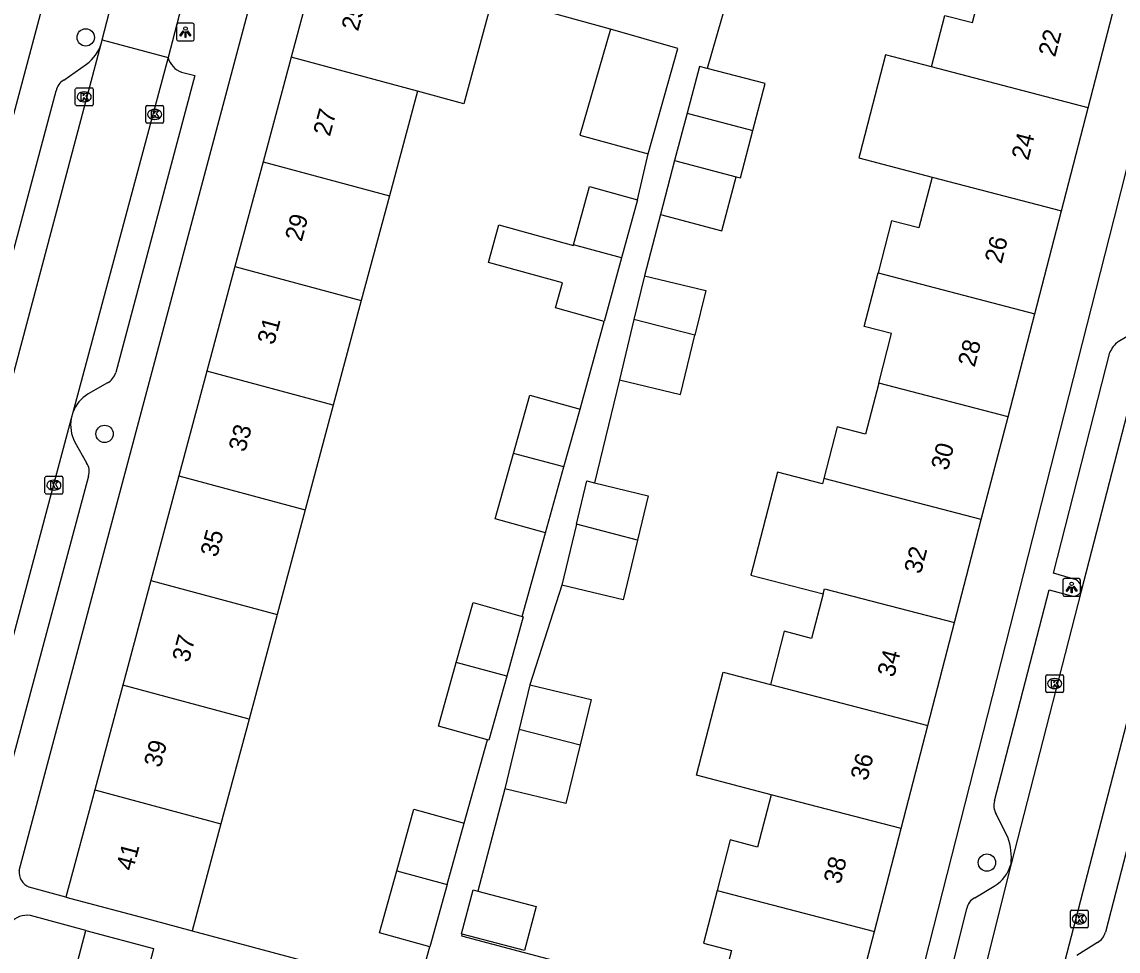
# Model space of a CAD drawing. Extents: x 163686 to 164493, y 382719 to 383870.
# Drawn here: x 163816.8 to 163878.6, y 383177.8 to 383230.2 of the extents above; entities that cross this region are included whole.
import ezdxf

# ---------------------------------------------------------------- set-up
doc = ezdxf.new("R2010")
doc.units = 0
for name, color, linetype in [('IMGEO_Boom', 7, 'Continuous'), ('IMGEO_Kolk', 7, 'Continuous'), ('IMGEO_Lichtpunt', 7, 'Continuous'), ('IMGEO_Pand', 7, 'Continuous'), ('IMGEO_Pand_nummerreeks', 7, 'Continuous'), ('IMGEO_Rijbaan_lokaal_open', 7, 'Continuous'), ('IMGEO_Voetpad_open', 7, 'Continuous')]:
    doc.layers.add(name, color=color, linetype=linetype)

msp = doc.modelspace()

# ---------------------------------------------------------------- linework, layer by layer
at = {"layer": 'IMGEO_Boom'}
for centre in [(163820.356, 383229.363), (163821.42, 383207), (163871.215, 383182.811)]:
    msp.add_circle(centre, 0.489, dxfattribs=at)
at = {"layer": 'IMGEO_Kolk'}
for p, q in [((163819.844, 383226.514), (163820.696, 383226.514)), ((163819.769, 383225.588), (163819.769, 383226.44)), ((163820.257, 383226.294), (163820.282, 383226.294)), ((163820.77, 383226.44), (163820.77, 383225.588)), ((163820.696, 383225.514), (163819.844, 383225.514)), ((163820.28, 383225.734), (163820.255, 383225.734)), ((163823.748, 383224.594), (163823.748, 383225.446)), ((163823.823, 383225.52), (163824.675, 383225.52)), ((163824.236, 383225.3), (163824.261, 383225.3)), ((163824.749, 383225.446), (163824.749, 383224.594)), ((163824.259, 383224.74), (163824.234, 383224.74)), ((163824.675, 383224.52), (163823.823, 383224.52)), ((163818.057, 383203.679), (163818.057, 383204.531)), ((163818.132, 383204.605), (163818.984, 383204.605)), ((163818.545, 383204.385), (163818.57, 383204.385)), ((163819.058, 383204.531), (163819.058, 383203.679)), ((163818.568, 383203.825), (163818.543, 383203.825)), ((163818.984, 383203.605), (163818.132, 383203.605)), ((163874.539, 383192.486), (163874.539, 383193.338)), ((163874.614, 383193.412), (163875.466, 383193.412)), ((163875.027, 383193.192), (163875.052, 383193.192)), ((163875.54, 383193.338), (163875.54, 383192.486)), ((163875.05, 383192.632), (163875.025, 383192.632)), ((163875.466, 383192.412), (163874.614, 383192.412)), ((163876.01, 383180.135), (163876.862, 383180.135)), ((163875.935, 383179.209), (163875.935, 383180.061)), ((163876.423, 383179.915), (163876.448, 383179.915)), ((163876.936, 383180.061), (163876.936, 383179.209)), ((163876.862, 383179.135), (163876.01, 383179.135)), ((163876.446, 383179.355), (163876.421, 383179.355))]:
    msp.add_line(p, q, dxfattribs=at)
for points in [[(163819.844, 383226.514), (163820.696, 383226.514)], [(163819.769, 383225.588), (163819.769, 383226.44)], [(163820.09, 383226.214), (163820.213, 383226.214), (163820.213, 383226.063), (163820.343, 383226.214), (163820.507, 383226.214), (163820.361, 383226.063), (163820.514, 383225.814), (163820.362, 383225.814), (163820.277, 383225.978), (163820.213, 383225.911), (163820.213, 383225.814), (163820.09, 383225.814), (163820.09, 383226.214)], [(163820.77, 383226.44), (163820.77, 383225.588)], [(163820.696, 383225.514), (163819.844, 383225.514)], [(163823.748, 383224.594), (163823.748, 383225.446)], [(163823.823, 383225.52), (163824.675, 383225.52)], [(163824.749, 383225.446), (163824.749, 383224.594)], [(163824.069, 383225.22), (163824.192, 383225.22), (163824.192, 383225.069), (163824.322, 383225.22), (163824.486, 383225.22), (163824.34, 383225.069), (163824.493, 383224.82), (163824.341, 383224.82), (163824.256, 383224.984), (163824.192, 383224.917), (163824.192, 383224.82), (163824.069, 383224.82), (163824.069, 383225.22)], [(163824.675, 383224.52), (163823.823, 383224.52)], [(163818.057, 383203.679), (163818.057, 383204.531)], [(163818.132, 383204.605), (163818.984, 383204.605)], [(163818.378, 383204.305), (163818.501, 383204.305), (163818.501, 383204.154), (163818.631, 383204.305), (163818.795, 383204.305), (163818.649, 383204.154), (163818.802, 383203.905), (163818.65, 383203.905), (163818.565, 383204.069), (163818.501, 383204.002), (163818.501, 383203.905), (163818.378, 383203.905), (163818.378, 383204.305)], [(163819.058, 383204.531), (163819.058, 383203.679)], [(163818.984, 383203.605), (163818.132, 383203.605)], [(163874.539, 383192.486), (163874.539, 383193.338)], [(163874.614, 383193.412), (163875.466, 383193.412)], [(163874.86, 383193.112), (163874.983, 383193.112), (163874.983, 383192.961), (163875.113, 383193.112), (163875.277, 383193.112), (163875.131, 383192.961), (163875.284, 383192.712), (163875.132, 383192.712), (163875.047, 383192.876), (163874.983, 383192.809), (163874.983, 383192.712), (163874.86, 383192.712), (163874.86, 383193.112)], [(163875.54, 383193.338), (163875.54, 383192.486)], [(163875.466, 383192.412), (163874.614, 383192.412)], [(163876.01, 383180.135), (163876.862, 383180.135)], [(163875.935, 383179.209), (163875.935, 383180.061)], [(163876.256, 383179.835), (163876.379, 383179.835), (163876.379, 383179.684), (163876.509, 383179.835), (163876.673, 383179.835), (163876.527, 383179.684), (163876.68, 383179.435), (163876.528, 383179.435), (163876.443, 383179.599), (163876.379, 383179.532), (163876.379, 383179.435), (163876.256, 383179.435), (163876.256, 383179.835)], [(163876.936, 383180.061), (163876.936, 383179.209)], [(163876.862, 383179.135), (163876.01, 383179.135)]]:
    msp.add_lwpolyline(points, dxfattribs=at)
for centre, start, end in [((163819.846, 383226.438), 91.55205, 178.44795), ((163819.846, 383226.438), 91.55205, 178.44795), ((163820.694, 383226.438), 1.55205, 88.44795), ((163820.694, 383226.438), 1.55205, 88.44795), ((163819.846, 383225.59), 181.55205, 268.44795), ((163819.846, 383225.59), 181.55205, 268.44795), ((163820.694, 383225.59), 271.55205, 358.44795), ((163820.694, 383225.59), 271.55205, 358.44795), ((163823.825, 383225.444), 91.55205, 178.44795), ((163823.825, 383225.444), 91.55205, 178.44795), ((163824.673, 383225.444), 1.55205, 88.44795), ((163824.673, 383225.444), 1.55205, 88.44795), ((163823.825, 383224.596), 181.55205, 268.44795), ((163823.825, 383224.596), 181.55205, 268.44795), ((163824.673, 383224.596), 271.55205, 358.44795), ((163824.673, 383224.596), 271.55205, 358.44795), ((163818.134, 383204.529), 91.55205, 178.44795), ((163818.134, 383204.529), 91.55205, 178.44795), ((163818.982, 383204.529), 1.55205, 88.44795), ((163818.982, 383204.529), 1.55205, 88.44795), ((163818.134, 383203.681), 181.55205, 268.44795), ((163818.134, 383203.681), 181.55205, 268.44795), ((163818.982, 383203.681), 271.55205, 358.44795), ((163818.982, 383203.681), 271.55205, 358.44795), ((163874.616, 383193.336), 91.55205, 178.44795), ((163874.616, 383193.336), 91.55205, 178.44795), ((163875.464, 383193.336), 1.55205, 88.44795), ((163875.464, 383193.336), 1.55205, 88.44795), ((163874.616, 383192.488), 181.55205, 268.44795), ((163874.616, 383192.488), 181.55205, 268.44795), ((163875.464, 383192.488), 271.55205, 358.44795), ((163875.464, 383192.488), 271.55205, 358.44795), ((163876.012, 383180.059), 91.55205, 178.44795), ((163876.012, 383180.059), 91.55205, 178.44795), ((163876.86, 383180.059), 1.55205, 88.44795), ((163876.86, 383180.059), 1.55205, 88.44795), ((163876.012, 383179.211), 181.55205, 268.44795), ((163876.012, 383179.211), 181.55205, 268.44795), ((163876.86, 383179.211), 271.55205, 358.44795), ((163876.86, 383179.211), 271.55205, 358.44795)]:
    msp.add_arc(centre, 0.0765, start, end, dxfattribs=at)
for centre, major_axis, ratio, start_param, end_param in [((163820.256, 383226.014), (-0.387, 0.002), 0.722429, 4.712389, 7.853982), ((163820.281, 383226.014), (-0.39, 0.002), 0.717154, 1.570796, 4.712389), ((163824.235, 383225.02), (-0.387, 0.002), 0.722429, 4.712389, 7.853982), ((163824.26, 383225.02), (-0.39, 0.002), 0.717154, 1.570796, 4.712389), ((163818.544, 383204.105), (-0.387, 0.002), 0.722429, 4.712389, 7.853982), ((163818.569, 383204.105), (-0.39, 0.002), 0.717154, 1.570796, 4.712389), ((163875.026, 383192.912), (-0.387, 0.002), 0.722429, 4.712389, 7.853982), ((163875.051, 383192.912), (-0.39, 0.002), 0.717154, 1.570796, 4.712389), ((163876.422, 383179.635), (-0.387, 0.002), 0.722429, 4.712389, 7.853982), ((163876.447, 383179.635), (-0.39, 0.002), 0.717154, 1.570796, 4.712389)]:
    msp.add_ellipse(centre, major_axis=major_axis, ratio=ratio, start_param=start_param, end_param=end_param, dxfattribs=at)
at = {"layer": 'IMGEO_Lichtpunt'}
for p, q in [((163825.484, 383230.071), (163825.484, 383229.264)), ((163825.484, 383230.071), (163825.484, 383229.264)), ((163826.386, 383230.166), (163825.578, 383230.166)), ((163826.386, 383230.166), (163825.578, 383230.166)), ((163826.48, 383229.264), (163826.48, 383230.071)), ((163826.48, 383229.264), (163826.48, 383230.071)), ((163825.578, 383229.17), (163826.386, 383229.17)), ((163825.578, 383229.17), (163826.386, 383229.17)), ((163875.496, 383198.738), (163875.496, 383197.931)), ((163875.496, 383198.738), (163875.496, 383197.931)), ((163876.398, 383198.833), (163875.59, 383198.833)), ((163876.398, 383198.833), (163875.59, 383198.833)), ((163876.492, 383197.931), (163876.492, 383198.738)), ((163876.492, 383197.931), (163876.492, 383198.738)), ((163875.59, 383197.837), (163876.398, 383197.837)), ((163875.59, 383197.837), (163876.398, 383197.837))]:
    msp.add_line(p, q, dxfattribs=at)
for points in [[(163825.858, 383229.735), (163825.897, 383229.707), (163825.709, 383229.445), (163825.671, 383229.472), (163825.858, 383229.735)], [(163825.96, 383229.687), (163826.007, 383229.687), (163826.007, 383229.365), (163825.96, 383229.365), (163825.96, 383229.687)], [(163826.07, 383229.707), (163826.108, 383229.734), (163826.295, 383229.472), (163826.256, 383229.444), (163826.07, 383229.707)], [(163875.87, 383198.402), (163875.909, 383198.374), (163875.721, 383198.112), (163875.683, 383198.139), (163875.87, 383198.402)], [(163875.972, 383198.354), (163876.019, 383198.354), (163876.019, 383198.032), (163875.972, 383198.032), (163875.972, 383198.354)], [(163876.082, 383198.374), (163876.12, 383198.401), (163876.307, 383198.139), (163876.268, 383198.111), (163876.082, 383198.374)]]:
    msp.add_lwpolyline(points, dxfattribs=at)
for centre in [(163825.983, 383229.869), (163875.995, 383198.536)]:
    msp.add_circle(centre, 0.0994, dxfattribs=at)
for centre, start, end in [((163825.578, 383230.071), 90, 180), ((163825.578, 383230.071), 90, 180), ((163826.386, 383230.071), 0, 90), ((163826.386, 383230.071), 0, 90), ((163825.578, 383229.264), 180, 270), ((163825.578, 383229.264), 180, 270), ((163826.386, 383229.264), 270, 0), ((163826.386, 383229.264), 270, 360), ((163875.59, 383198.738), 90, 180), ((163875.59, 383198.738), 90, 180), ((163876.398, 383198.738), 0, 90), ((163876.398, 383198.738), 0, 90), ((163875.59, 383197.931), 180, 270), ((163875.59, 383197.931), 180, 270), ((163876.398, 383197.931), 270, 0), ((163876.398, 383197.931), 270, 360)]:
    msp.add_arc(centre, 0.0946, start, end, dxfattribs=at)
at = {"layer": 'IMGEO_Pand'}
for points in [[(163833.569, 383234.29), (163831.947, 383228.242)], [(163868.09, 383227.699), (163868.846, 383230.61), (163870.404, 383230.205), (163871.156, 383233.102)], [(163843.325, 383231.674), (163841.703, 383225.626), (163839.075, 383226.331)], [(163876.933, 383225.397), (163878.441, 383231.206)], [(163849.976, 383229.828), (163848.249, 383223.846), (163852.097, 383222.796)], [(163852.097, 383222.796), (163853.773, 383228.738), (163849.976, 383229.828)], [(163868.09, 383227.699), (163865.494, 383228.375), (163864.036, 383222.777), (163863.981, 383222.566), (163868.118, 383221.489)], [(163831.947, 383228.242), (163830.363, 383222.339)], [(163839.075, 383226.331), (163831.947, 383228.242)], [(163855.424, 383227.614), (163854.986, 383227.729), (163854.293, 383225.088)], [(163858.005, 383224.122), (163858.696, 383226.756), (163855.424, 383227.614)], [(163876.933, 383225.397), (163868.09, 383227.699)], [(163839.075, 383226.331), (163837.491, 383220.427)], [(163875.424, 383219.587), (163876.933, 383225.397)], [(163854.293, 383225.088), (163853.592, 383222.413)], [(163854.293, 383225.088), (163854.427, 383225.053), (163858.005, 383224.122)], [(163857.058, 383221.504), (163857.302, 383221.44), (163858.005, 383224.122)], [(163830.363, 383222.339), (163828.779, 383216.436)], [(163830.363, 383222.339), (163837.491, 383220.427)], [(163853.592, 383222.413), (163852.794, 383219.37)], [(163853.592, 383222.413), (163857.058, 383221.504)], [(163847.884, 383217.657), (163848.793, 383220.952), (163851.501, 383220.205)], [(163852.794, 383219.37), (163856.26, 383218.462), (163857.058, 383221.504)], [(163868.118, 383221.489), (163867.372, 383218.617), (163865.838, 383219.016), (163865.076, 383216.079)], [(163868.118, 383221.489), (163875.424, 383219.587)], [(163837.491, 383220.427), (163835.907, 383214.524)], [(163851.501, 383220.205), (163850.597, 383216.93)], [(163873.915, 383213.778), (163875.424, 383219.587)], [(163849.608, 383213.345), (163846.868, 383214.101), (163847.26, 383215.521), (163843.08, 383216.674), (163843.664, 383218.789), (163847.876, 383217.628), (163847.884, 383217.657)], [(163850.597, 383216.93), (163847.884, 383217.657)], [(163850.597, 383216.93), (163849.608, 383213.345)], [(163828.779, 383216.436), (163827.195, 383210.532)], [(163828.779, 383216.436), (163835.907, 383214.524)], [(163865.111, 383209.867), (163865.837, 383212.662), (163864.293, 383213.063), (163865.076, 383216.079)], [(163865.076, 383216.079), (163873.915, 383213.778)], [(163851.892, 383215.923), (163851.298, 383213.46)], [(163851.892, 383215.923), (163855.346, 383215.09), (163854.737, 383212.566)], [(163835.907, 383214.524), (163834.324, 383208.621)], [(163872.407, 383207.969), (163873.915, 383213.778)], [(163851.298, 383213.46), (163850.474, 383210.044)], [(163854.737, 383212.566), (163851.298, 383213.46)], [(163850.474, 383210.044), (163853.928, 383209.211), (163854.737, 383212.566)], [(163827.195, 383210.532), (163825.612, 383204.629)], [(163834.324, 383208.621), (163827.195, 383210.532)], [(163865.111, 383209.867), (163864.364, 383206.99), (163862.77, 383207.404), (163862.009, 383204.473)], [(163872.407, 383207.969), (163865.111, 383209.867)], [(163834.324, 383208.621), (163832.74, 383202.718)], [(163844.498, 383205.894), (163845.417, 383209.178), (163848.256, 383208.384)], [(163847.346, 383205.13), (163848.256, 383208.384)], [(163870.898, 383202.16), (163872.407, 383207.969)], [(163846.306, 383201.411), (163843.467, 383202.205), (163844.498, 383205.894)], [(163847.346, 383205.13), (163844.498, 383205.894)], [(163846.306, 383201.411), (163847.346, 383205.13)], [(163825.612, 383204.629), (163824.028, 383198.725)], [(163825.612, 383204.629), (163832.74, 383202.718)], [(163848.053, 383201.902), (163848.642, 383204.342), (163849.074, 383204.238)], [(163862.009, 383204.473), (163861.932, 383204.175), (163859.402, 383204.832), (163857.896, 383199.029), (163861.97, 383197.972)], [(163870.898, 383202.16), (163862.009, 383204.473)], [(163849.074, 383204.238), (163852.096, 383203.509), (163851.493, 383201.007)], [(163832.74, 383202.718), (163831.156, 383196.814)], [(163848.053, 383201.902), (163847.224, 383198.463)], [(163851.493, 383201.007), (163848.053, 383201.902)], [(163869.389, 383196.35), (163870.898, 383202.16)], [(163851.493, 383201.007), (163850.678, 383197.629), (163847.224, 383198.463)], [(163824.028, 383198.725), (163822.444, 383192.823)], [(163824.028, 383198.725), (163831.156, 383196.814)], [(163861.97, 383197.972), (163862.045, 383198.261), (163869.389, 383196.35)], [(163841.268, 383194.103), (163842.213, 383197.48), (163844.989, 383196.704)], [(163861.97, 383197.972), (163861.318, 383195.462), (163859.779, 383195.861), (163858.998, 383192.853)], [(163831.156, 383196.814), (163829.573, 383190.911)], [(163844.989, 383196.704), (163845.052, 383196.686), (163844.116, 383193.339)], [(163867.88, 383190.541), (163869.389, 383196.35)], [(163843.037, 383189.731), (163840.263, 383190.508), (163841.268, 383194.103)], [(163844.116, 383193.339), (163841.268, 383194.103)], [(163844.116, 383193.339), (163843.102, 383189.713), (163843.037, 383189.731)], [(163859.034, 383186.642), (163854.82, 383187.739), (163856.331, 383193.547), (163858.998, 383192.853)], [(163822.444, 383192.823), (163820.861, 383186.919)], [(163829.573, 383190.911), (163822.444, 383192.823)], [(163845.422, 383192.849), (163844.817, 383190.343)], [(163845.422, 383192.849), (163848.876, 383192.016), (163848.256, 383189.447)], [(163858.998, 383192.853), (163867.88, 383190.541)], [(163829.573, 383190.911), (163827.989, 383185.008)], [(163844.817, 383190.343), (163844.003, 383186.97)], [(163844.817, 383190.343), (163848.256, 383189.447)], [(163866.372, 383184.732), (163867.88, 383190.541)], [(163848.256, 383189.447), (163847.458, 383186.137), (163844.003, 383186.97)], [(163820.861, 383186.919), (163819.238, 383180.871)], [(163820.861, 383186.919), (163827.989, 383185.008)], [(163859.034, 383186.642), (163858.268, 383183.692), (163856.733, 383184.091), (163855.991, 383181.232)], [(163866.372, 383184.732), (163859.034, 383186.642)], [(163837.909, 383182.348), (163838.882, 383185.825), (163841.721, 383185.031)], [(163827.989, 383185.008), (163826.366, 383178.959)], [(163840.757, 383181.585), (163841.721, 383185.031)], [(163864.863, 383178.923), (163866.372, 383184.732)], [(163839.771, 383178.058), (163836.932, 383178.852), (163837.909, 383182.348)], [(163837.909, 383182.348), (163840.757, 383181.585)], [(163840.757, 383181.585), (163839.771, 383178.058)], [(163819.238, 383180.871), (163824.068, 383179.575), (163826.366, 383178.959)], [(163841.592, 383178.782), (163841.566, 383178.789), (163842.222, 383181.276), (163842.483, 383181.207)], [(163842.483, 383181.207), (163845.783, 383180.337), (163845.126, 383177.849), (163841.592, 383178.782)], [(163855.991, 383181.232), (163855.221, 383178.269), (163856.794, 383177.861), (163856.017, 383174.866)], [(163855.991, 383181.232), (163864.863, 383178.923)], [(163824.144, 383177.793), (163823.421, 383175.099), (163819.601, 383176.124), (163820.368, 383178.983)], [(163820.368, 383178.983), (163824.188, 383177.958), (163824.144, 383177.793)], [(163863.317, 383172.97), (163864.863, 383178.923)]]:
    msp.add_lwpolyline(points, dxfattribs=at)
at = {"layer": 'IMGEO_Rijbaan_lokaal_open'}
for points in [[(163821.284, 383229.236), (163822.316, 383233.238), (163822.389, 383233.509)], [(163826.124, 383232.512), (163825.009, 383228.231)], [(163815.899, 383208.952), (163821.224, 383229.007)], [(163821.224, 383229.007), (163821.257, 383229.134), (163821.284, 383229.236)], [(163821.284, 383229.236), (163825.009, 383228.231)], [(163825.009, 383228.231), (163819.632, 383208.209)], [(163880.556, 383213.687), (163876.544, 383198.126)], [(163819.632, 383208.209), (163819.538, 383207.865)], [(163819.538, 383207.865), (163813.306, 383184.59)], [(163875.48, 383176.702), (163881.547, 383200.035)], [(163876.544, 383198.126), (163872.577, 383182.742)], [(163872.577, 383182.742), (163867.673, 383163.156), (163865.433, 383150.514)]]:
    msp.add_lwpolyline(points, dxfattribs=at)
at = {"layer": 'IMGEO_Voetpad_open'}
for points in [[(163824.418, 383255.554), (163805.809, 383185.829)], [(163885.219, 383245.624), (163880.342, 383226.864), (163878.372, 383219.125), (163866.423, 383172.179)], [(163816.591, 383182.375), (163829.711, 383231.555), (163830.648, 383235.069)], [(163857.047, 383233.238), (163855.424, 383227.614)], [(163849.976, 383229.828), (163843.325, 383231.674)], [(163819.118, 383226.956), (163820.405, 383227.862)], [(163825.762, 383227.397), (163826.517, 383227.212), (163822.055, 383210.455)], [(163815.535, 383209.42), (163814.242, 383209.793), (163818.681, 383226.35)], [(163851.501, 383220.205), (163852.097, 383222.796)], [(163852.794, 383219.37), (163851.892, 383215.923)], [(163848.256, 383208.384), (163849.608, 383213.345)], [(163878.618, 383212.203), (163879.775, 383212.88)], [(163876.26, 383198.764), (163874.967, 383199.137), (163878.16, 383211.586)], [(163821.58, 383209.869), (163820.496, 383209.249)], [(163850.474, 383210.044), (163849.074, 383204.238)], [(163819.742, 383206.54), (163820.404, 383205.362)], [(163820.515, 383204.612), (163815.779, 383186.943)], [(163844.989, 383196.704), (163846.306, 383201.411)], [(163847.224, 383198.463), (163845.422, 383192.849)], [(163871.646, 383186.302), (163874.737, 383198.209), (163875.989, 383197.861)], [(163882.596, 383197.021), (163877.902, 383178.894)], [(163841.721, 383185.031), (163843.037, 383189.731)], [(163844.003, 383186.97), (163842.483, 383181.207)], [(163872.396, 383184.243), (163871.734, 383185.547)], [(163819.238, 383180.871), (163817.17, 383181.426)], [(163870.525, 383180.827), (163871.629, 383181.488)], [(163864.198, 383153.637), (163865.933, 383163.501), (163870.083, 383180.214)], [(163820.368, 383178.983), (163817.248, 383179.82)], [(163826.366, 383178.959), (163839.073, 383175.562), (163839.771, 383178.058)], [(163841.592, 383178.782), (163841.566, 383178.682), (163845.1, 383177.749), (163856.017, 383174.866)], [(163877.452, 383178.3), (163876.291, 383177.57)]]:
    msp.add_lwpolyline(points, dxfattribs=at)
for centre, radius, start, end in [((163819.16, 383229.618), 2.152, 305.33725, 343.51169), ((163826.167, 383228.519), 1.193, 193.98614, 250.17021), ((163819.515, 383226.209), 0.845, 117.98011, 170.42748), ((163879.497, 383211.072), 1.432, 127.85154, 158.97535), ((163821.087, 383210.754), 1.013, 299.10609, 342.83883), ((163821.557, 383207.488), 2.056, 121.08217, 159.48031), ((163821.543, 383207.495), 2.038, 169.55517, 207.95015), ((163819.669, 383204.87), 0.885, 343.04281, 33.79451), ((163875.895, 383198.219), 0.656, 351.81476, 56.17686), ((163876.112, 383198.317), 0.472, 254.89907, 336.14778), ((163872.564, 383186.026), 0.958, 163.28586, 210.01051), ((163869.112, 383183.086), 3.482, 354.33762, 19.41415), ((163870.581, 383183.265), 2.063, 300.51582, 345.30701), ((163817.532, 383182.298), 0.944, 175.31281, 247.46325), ((163870.901, 383180.09), 0.827, 117.03585, 171.37762), ((163817.033, 383178.63), 1.209, 79.77994, 140.80801), ((163877.004, 383179.107), 0.922, 299.03027, 346.67635)]:
    msp.add_arc(centre, radius, start, end, dxfattribs=at)

# ---------------------------------------------------------------- texts
at = {"layer": 'IMGEO_Pand_nummerreeks'}
for s, rotation, p in [('25', 74.98257, (163835.726, 383229.675)), ('22', 75.44132, (163875.062, 383228.218)), ('27', 74.98257, (163834.133, 383223.739)), ('24', 75.44135, (163873.547, 383222.388)), ('29', 74.98257, (163832.541, 383217.804)), ('26', 75.44132, (163872.033, 383216.555)), ('31', 74.98257, (163830.979, 383211.978)), ('28', 75.44132, (163870.519, 383210.724)), ('33', 74.98257, (163829.356, 383205.933)), ('30', 75.44132, (163869.004, 383204.891)), ('35', 74.98257, (163827.764, 383199.998)), ('32', 75.44135, (163867.486, 383199.051)), ('37', 74.98257, (163826.172, 383194.062)), ('34', 75.44135, (163865.972, 383193.221)), ('39', 74.98257, (163824.579, 383188.127)), ('36', 75.44132, (163864.458, 383187.388)), ('41', 74.98257, (163823.017, 383182.3)), ('38', 75.44132, (163862.944, 383181.557))]:
    msp.add_text(s, height=1, rotation=rotation, dxfattribs=at).set_placement(p)

doc.saveas('drawing.dxf')
